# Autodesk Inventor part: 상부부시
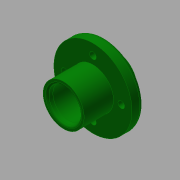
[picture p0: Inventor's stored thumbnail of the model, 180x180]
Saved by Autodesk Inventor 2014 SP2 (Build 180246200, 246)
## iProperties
Created: 2015-12
Part Number: 상부부시
Material: 강철, 연강
Document SubType Name: Modeling
Designer: mduedu
Density: 7.86 g/cm^3
Appearance: 진녹색
Author: mduedu
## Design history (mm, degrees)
sketch "스케치1"
  geometry: C1 r 10.5 at (0, 0); C2 r 8 at (0, 0); 1 further point
  constraints: 2 centre point, 2 coincident
  dimensions: "d1" = 21 diameter of C1; "d3" = 16 diameter of C2
extrude "돌출1" new body sketch "스케치1" distance "d4" = 12; taper "d6" = 0 deg; dims "d5" = 15, "d7" = 0
sketch "스케치2"
  geometry: C1 r 20 at (0, 0); C2 r 10.5 at (0, 0) reference; 1 further point
  constraints: 1 centre point, 1 coincident
  dimensions: "d8" = 40 diameter of C1
extrude "돌출2" join sketch "스케치2" distance "d10" = 6; taper "d11" = 0 deg
chamfer "모따기1" distance "d12" = 2.5; stored, may be unused: second distance "d13" = 2, angle "d14" = 10 deg
chamfer "모따기2" distance "d15" = 2.5; stored, may be unused: second distance "d16" = 2, angle "d17" = 10 deg
fillet "모깎기1" dims "d18" = 1
fillet "모깎기2" dims "d19" = 2
sketch "스케치3" dims "d20" = 29
  geometry: 6 further points
  constraints: 2 vertical alignment, 1 coincident, 7 other
  dimensions: "d24" = 360 deg dimension on point (0, 0) point (0, 14.5) (derived)
sketch "스케치4"
  geometry: 4 further points
hole "구멍1" sketch "스케치4" at (-14.5, 0), (0, -14.5), (14.5, 0), (0, 14.5) diameter "d26" = 3.4; stored, may be unused: countersink angle "d30" = 90 deg, drill point angle "d32" = 0 deg; dims "d27" = 6, "d28" = 6.5, "d29" = 3.4, "d31" = 8
fillet "모깎기3" dims "d33" = 1
node "솔리드1"
